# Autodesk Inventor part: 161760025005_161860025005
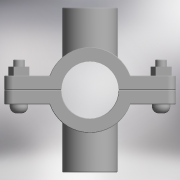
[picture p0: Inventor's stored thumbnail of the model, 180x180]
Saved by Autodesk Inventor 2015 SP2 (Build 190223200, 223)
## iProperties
Created: 2017-05
Part Number: 161760025005_161860025005
Material: Generic
Description: PLASSON DOUBLE SADDLE 25-1/2"
Document SubType Name: Modeling
Designer: KIM
Density: 1 g/cm^3
Appearance: Default
Author: KIM
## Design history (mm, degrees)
derived "16176.ipt"
feature "Solid1::16176.ipt"
feature "Solid2::16176.ipt"
tag "TaggingFeature1"
body "Solid1"
body "Solid2"
other parameters: "d0" = 37.5, "d1" = 75, "d2" = 12.5, "d3" = 25, "d5" = 0, "d6" = 3.75, "d7" = 75, "d8" = 0.1, "d10" = 0, "d11" = 0.25, "d20" = 0.25, "d23" = 0.25, "d36" = 8, "d37" = 6.4, "d38" = 20.5, "d39" = 0, "d40" = 3, "d41" = 4, "d42" = 0, "d43" = 5, "d44" = 3, "d45" = 0, "d46" = 0.25, "d52" = 18.631, "d53" = 18, "d54" = 0, "d55" = 15, "d57" = 0, "d58" = 27, "d60" = 0, "d62" = 8, "d63" = 25, "d66" = 0, "d67" = 72, "d68" = 24.2203, "d69" = 18.631, "d70" = 18, "d71" = 0, "d72" = 15, "d74" = 0, "d75" = 0.25, "d_" = 25, "B_" = 15, "G_" = 18.631, "A_" = 36, "L_" = 75, "l_2" = 18
